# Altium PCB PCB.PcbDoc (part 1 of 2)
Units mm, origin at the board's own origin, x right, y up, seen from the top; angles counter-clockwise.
Board outline 68.58 x 53.34 mm, 2 copper layers (TOP, BOTTOM), stack 1.636 mm thick; 84 components, 64 nets, 302 pads, 163 vias.
Unrouted connection lines stored in the file: 1.
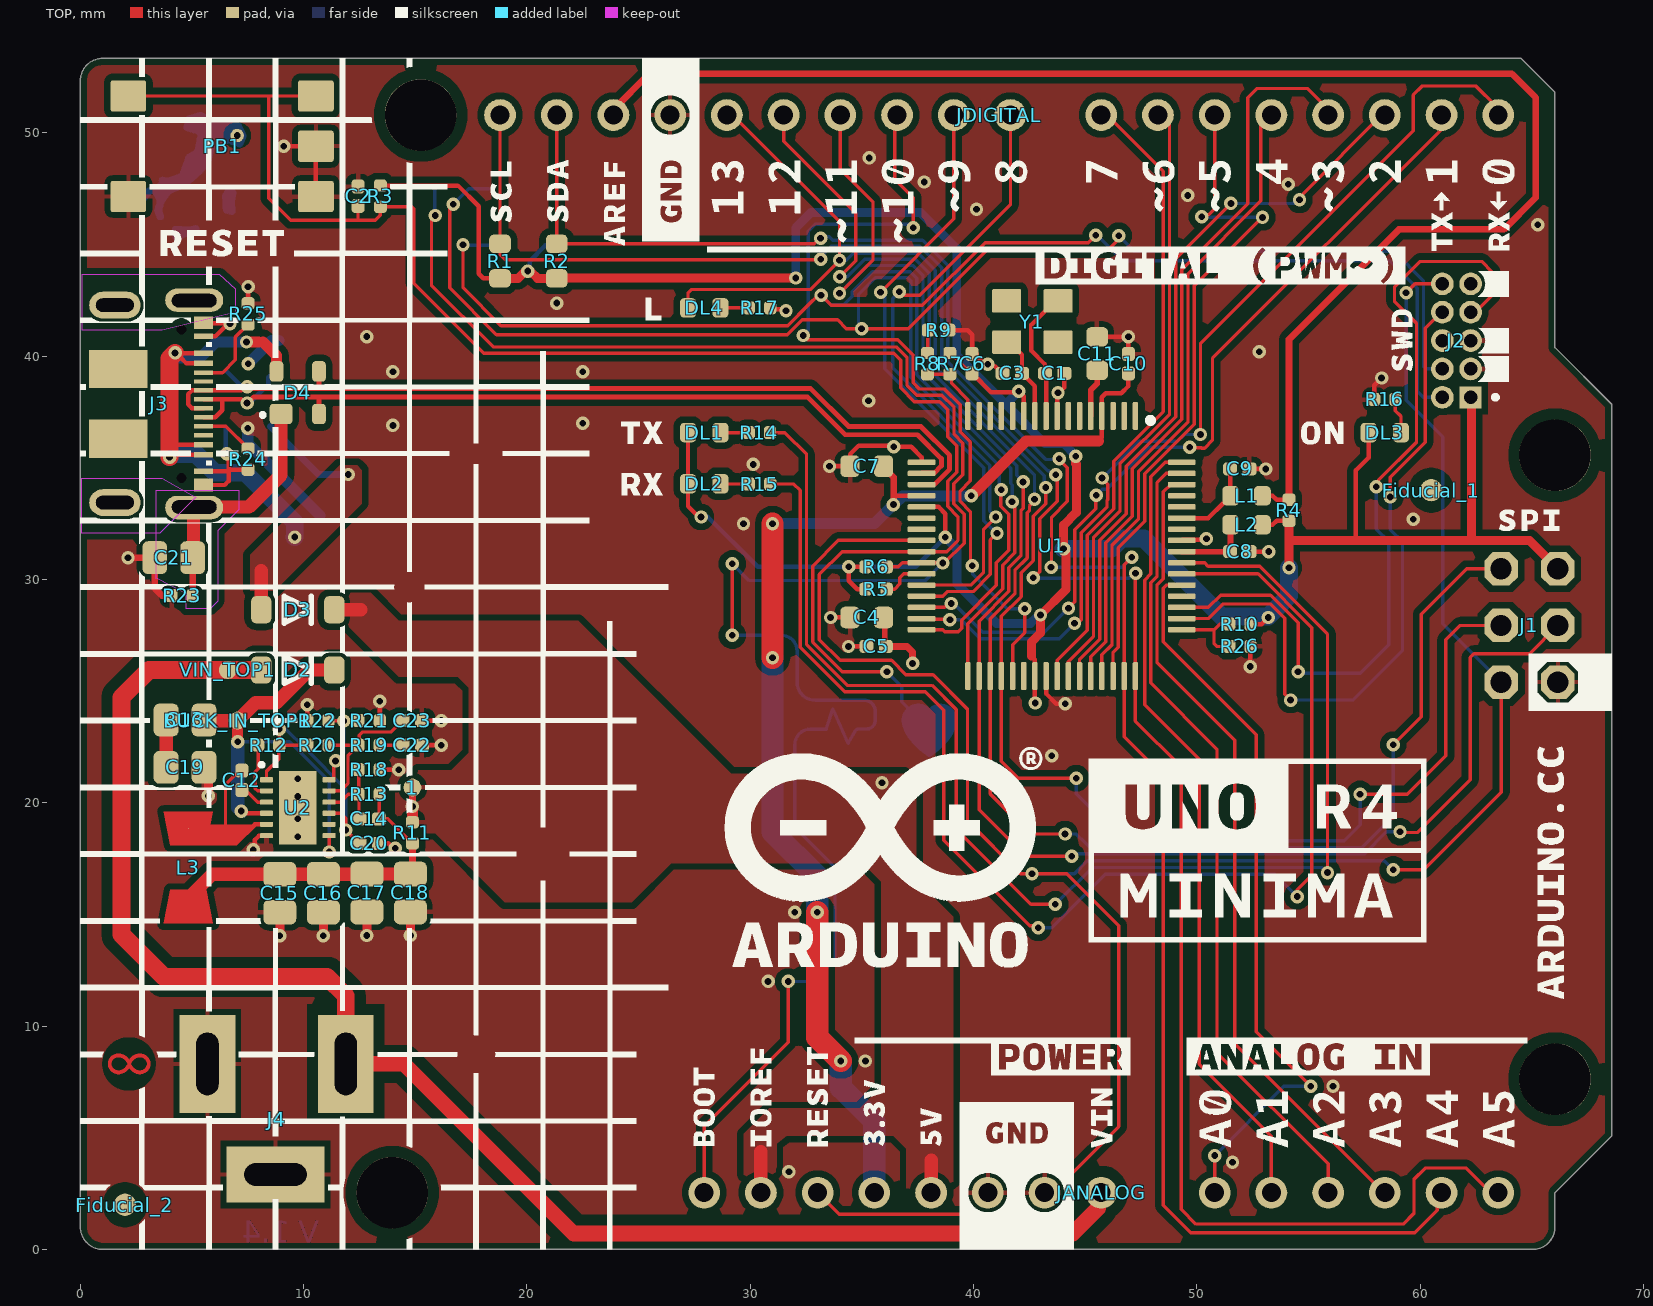
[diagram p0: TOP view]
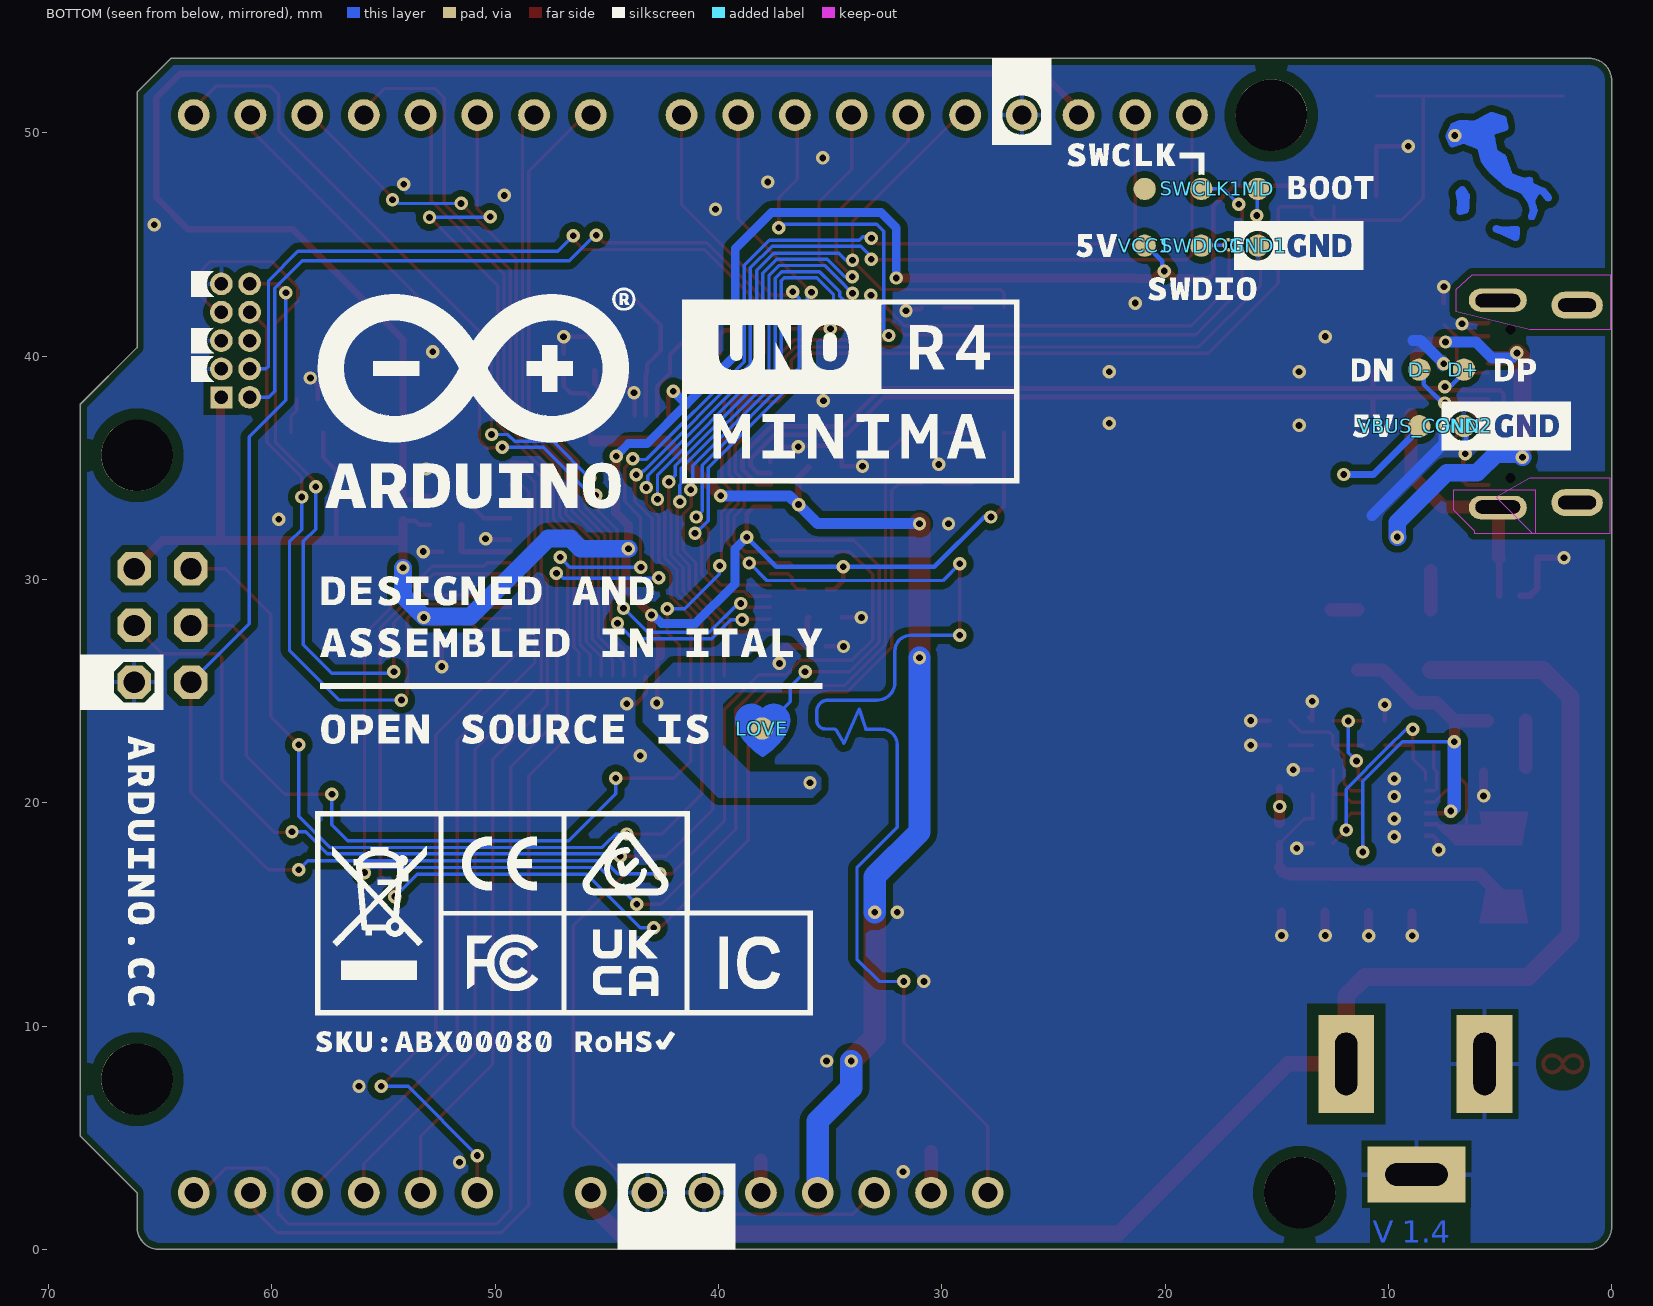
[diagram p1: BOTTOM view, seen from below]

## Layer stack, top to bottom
Top Solder: solder mask 0.025, SM-003, Dk 4
TOP: signal copper 0.018
Dielectric2: core 1.6, FR-4, Dk 4.8
BOTTOM: signal copper 0.018
Bottom Solder: solder mask 0.025, SM-003, Dk 4

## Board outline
0,1 0,52.34 cw(c1,52.34) 1,53.34 64.516,53.34 66.04,51.816 66.04,40.386 68.58,37.846 68.58,5.08 66.04,2.54 66.04,1 cw(c65.04,1) 65.04,0 1,0 cw(c1,1)

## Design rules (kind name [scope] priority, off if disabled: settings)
BoardOutlineClearance Mousebites [(ObjectKind = 'Pad') And (Name = 'Free-MOUSEBITE')] p1: gap=0 ignorepadtopadclearanceinfootprint=FALSE
BoardOutlineClearance Silks [(OnLayer('Top Overlay') OR OnLayer('Bottom Overlay'))] p2: gap=0 ignorepadtopadclearanceinfootprint=FALSE
BoardOutlineClearance [All] p3: gap=0.3 ignorepadtopadclearanceinfootprint=FALSE
Clearance [(ObjectKind = 'Region') And (Net = 'No Net') And (Area = '1.358 sq.')] p1: gap=0.15 ignorepadtopadclearanceinfootprint=FALSE
Clearance MH [(ObjectKind = 'Pad') And (Name = 'Free-MH')] p2: gap=0.5 ignorepadtopadclearanceinfootprint=FALSE
Clearance COPPER_0.3mm_VIN [InNet('GND') vs InNet('VIN')] p3: gap=0.5 ignorepadtopadclearanceinfootprint=TRUE except(0.127: Arc-Arc Arc-Track Arc-SMDPad Arc-THPad Arc-Via Arc-Text Arc-Hole Track-Track Track-SMDPad Track-THPad Track-Via Track-Text Track-Hole SMDPad-SMDPad SMDPad-THPad SMDPad-Via SMDPad-Text SMDPad-Hole THPad-THPad THPad-Via THPad-Text THPad-Hole Via-Via Via-Text Via-Hole Fill-Hole Poly-Hole Region-Hole Text-Text Text-Hole)
Clearance COPPER_0.3mm [All] p4: gap=0.127 ignorepadtopadclearanceinfootprint=FALSE except(0.3: Arc-Fill Arc-Poly Arc-Region Track-Fill Track-Poly Track-Region SMDPad-Fill SMDPad-Poly SMDPad-Region THPad-Fill THPad-Poly THPad-Region Via-Fill Via-Poly Via-Region Fill-Fill Fill-Poly Fill-Region Poly-Poly Poly-Region Region-Region)
Clearance "Generic clearance 0.15mm" [All] p5: gap=0.15 ignorepadtopadclearanceinfootprint=FALSE
ComponentClearance DoubleResP119 [(ObjectKind = 'Component') And (Name = 'R119') vs (ObjectKind = 'Component') And (Name = 'R120')] p1: gap=0 collisioncheckmode=3 verticalgap=0 showdistances=FALSE
ComponentClearance DoubleResP300 [(ObjectKind = 'Component') And (Name = 'R117') vs (ObjectKind = 'Component') And (Name = 'R115')] p2: gap=0 collisioncheckmode=3 verticalgap=0 showdistances=FALSE
ComponentClearance DoubleResP108 [(ObjectKind = 'Component') And (Name = 'R114') vs (ObjectKind = 'Component') And (Name = 'R116')] p3: gap=0 collisioncheckmode=3 verticalgap=0 showdistances=FALSE
ComponentClearance ComponentClearance_2 [InComponent('J4')] p4: gap=0 collisioncheckmode=3 verticalgap=0 showdistances=FALSE
ComponentClearance ComponentClearance_1 [InComponent('Fiducial_2') vs InComponent('J3')] p5: gap=0 collisioncheckmode=3 verticalgap=0 showdistances=FALSE
ComponentClearance [All] p6: gap=0.2 collisioncheckmode=3 verticalgap=0 showdistances=TRUE
DiffPairsRouting USB [InDifferentialPairClass('USB')] p1: maxlimit=0.15 minlimit=0.15 mostfreqgap=0.15 toplayer_minwidth=0.22 toplayer_maxwidth=0.22 toplayer_prefwidth=0.22 bottomlayer_minwidth=0.2 bottomlayer_maxwidth=0.2 bottomlayer_prefwidth=0.2 impedanceprofiledriven=TRUE impedanceprofileid={E6B00C31-4C8E-439C-824F-D2B2CDC26F9C} impedanceprofilevalue=90.000000 maxuncoupledlength=12.7
Height [All] p1: minheight=0 maxheight=30 prefheight=12.7
HoleSize [All] p1: absolutevalues=TRUE maxlimit=30 minlimit=0.3 maxpercent=80.000 minpercent=20.000
HoleToHoleClearance [All] p1: gap=0.25 allowstackedmicrovias=FALSE
MinimumAnnularRing [All] p1: minimumring=0.15
MinimumSolderMaskSliver [All] p1: minsoldermaskwidth=0.22
PlaneConnect [All] p1: pad.planeconnectstyle=Relief pad.reliefexpansion=0.508 pad.reliefentries=4 pad.reliefconductorwidth=0.254 pad.reliefairgap=0.254 via.planeconnectstyle=Direct via.reliefexpansion=0.508 via.reliefentries=4 via.reliefconductorwidth=0.254 via.reliefairgap=0.254
PolygonConnect [All] p1: thpad.connectstyle=Relief thpad.reliefconductorwidth=0.2 thpad.reliefentries=4 thpad.polygonreliefangle="90 Angle" thpad.airgapwidth=0.254 smdpad.connectstyle=Relief smdpad.reliefconductorwidth=0.2 smdpad.reliefentries=4 smdpad.polygonreliefangle="90 Angle" smdpad.airgapwidth=0.254 via.connectstyle=Direct via.reliefconductorwidth=0.254 via.reliefentries=4 via.polygonreliefangle="90 Angle" via.airgapwidth=0.254
RoomDefinition designers_1 [False vs False] p1: confinementstyle=ConfineIn formatcopy=TRUE lockcomponents=FALSE outline 0.4,10.2 4,10.2 4,5.8 0.4,5.8
RoomDefinition TOP [InComponentClass('TOP')] p2: confinementstyle=ConfineIn formatcopy=TRUE lockcomponents=FALSE outline 69.7,-1.1 85.9,-1.1 85.9,12.7 69.7,12.7
RoutingVias StandardVias [All] p1: holewidth=0.3 width=0.6 viastyle="Through Hole" minholewidth=0.3 minwidth=0.6 maxholewidth=0.3 maxwidth=0.6
ShortCircuit SolderJumper [Component = 'SJ2' vs (InNet('VCC') OR InNet('NetL3_1'))] p1: allowed=TRUE
ShortCircuit [All] p2: allowed=FALSE
SilkToSilkClearance [All] p1: silktosilkclearance=0.2
SilkToSolderMaskClearance [IsPad] p1: minsilkscreentomaskgap=0.15 clearancetoexposedcopper=TRUE
SolderMaskExpansion VIAtented [IsVia] p1: expansion=0.102 istentingtop=TRUE
SolderMaskExpansion [All] p2: expansion=0.05 istentingtop=FALSE
UnConnectedPin [All] p1:
UnRoutedNet [NOT WithinRoom('designers_1')] p1: checkbadconnections=TRUE
ViasUnderSMD [All] p1: allowed=FALSE
Width StandardTraces [All] p1: maxlimit=5 minlimit=0.15 preferedwidth=0.15 minimp=50.000000 maximp=50.000000 favimp=50.000000
19 further rules are at their usual default settings.

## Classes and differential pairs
differential pair class USB: USB_D_1
differential pair USB_D_1: +USB_D_1_P -USB_D_1_N

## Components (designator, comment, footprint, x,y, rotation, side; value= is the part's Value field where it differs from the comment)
1 "CMP-018-0004-A.4" TP-0.8MM 14.873,20.682 r90 top
BUCK_IN_TOP1 "CMP-018-0004-A.4" TP-0.8MM 7.038,23.682 r90 top
C1 "C0402C150J5GACTU" CAP-0402 43.638,39.231 r0 top value=15pF
C2 "DNP" CAP-0402 12.438,47.166 r90 top
C3 "C0402C150J5GACTU" CAP-0402 41.738,39.231 r180 top value=15pF
C4 "GRM188R61C475KAAJD" CAP-0603 35.22,28.3 r0 top value=4.7µF
C5 "GRM155R61H104KE19D" CAP-0402 35.638,27 r0 top value=100nF
C6 "GRM155R61H104KE19D" CAP-0402 39.938,39.666 r270 top value=100nF
C7 "GRM188R61C475KAAJD" CAP-0603 35.22,35.076 r0 top value=4.7µF
C8 "GRM155R61H104KE19D" CAP-0402 51.928,31.25 r180 top value=100nF
C9 "CL05A105KP5NNNC" CAP-0402 51.928,34.95 r0 top value=1µF
C10 "GRM155R61H104KE19D" CAP-0402 46.938,39.666 r270 top value=100nF
C11 "GRM188R61C475KAAJD" CAP-0603 45.538,40.116 r270 top value=4.7µF
C12 "GRM155R61H104KE19D" CAP-0402 7.238,21.007 r270 top value=100nF
C13 "CL21A226MAQNNNE" CAP-0805 4.691,23.708 r0 top value=22µF
C14 "GRM1555C1H330JA01D" CAP-0402 12.938,19.282 r0 top value=33pF
C15 "CL21A226MAQNNNE" CAP-0805 8.936,15.947 r90 top value=22µF
C16 "CL21A226MAQNNNE" CAP-0805 10.886,15.947 r90 top value=22µF
C17 "CL21A226MAQNNNE" CAP-0805 12.834,15.962 r90 top value=22µF
C18 "CL21A226MAQNNNE" CAP-0805 14.784,15.962 r90 top value=22µF
C19 "CL21A226MAQNNNE" CAP-0805 4.691,21.591 r180 top value=22µF
C20 "CL05A105KP5NNNC" CAP-0402 12.938,18.182 r0 top value=1µF
C21 "FV21X472K102ECG" CAP-0805 4.184,30.978 r0 top value=4.7nF
C22 "GRM155R71H102KA01D" CAP-0402 14.873,22.582 r180 top value=1nF
C23 "CC0402JRNPO9BN101" CAP-0402 14.873,23.682 r180 top value=100pF
D2 "PMEG6020AELRX" SOD123-1 9.738,25.947 r180 top
D3 "PMEG6020AELRX" SOD123-1 9.738,28.647 r180 top
D4 "PRTR5V0U2X,215" SOT190P230X110-4N 9.738,38.366 r0 top
D+ "CMP-018-0005-A.3" TP-1.00MM#1 6.615,39.4 r180 bottom
D- "CMP-018-0005-A.3" TP-1.00MM#1 8.615,39.4 r180 bottom
DL1 "KPT-1608YC" LEDC1608X80N-AK#1 27.94,36.576 r180 top
DL2 "KPT-1608YC" LEDC1608X80N-AK#1 27.94,34.29 r180 top
DL3 "HSMG-C190" LEDC1608X80N-AK#2 58.42,36.576 r180 top
DL4 "KPT-1608YC" LEDC1608X80N-AK#1 27.94,42.164 r180 top
Fiducial_1 "Fiducial mark 1mm with 2mm solder" "Fiducial mark 1mm with circle-Footprint-1" 60.5,34 r90 top
Fiducial_2 "Fiducial mark 1mm with 2mm solder" "Fiducial mark 1mm with circle-Footprint-1" 2,2 r90 top
GND1 "CMP-018-0005-A.3" TP-1.00MM#2 15.835,44.95 r90 bottom
GND2 "CMP-018-0005-A.3" TP-1.00MM#1 6.615,36.875 r90 bottom
J1 "PH2-06-UA" 2X03 64.897,27.94 r90 top
J2 "HPH2-A-10-SGA" PINHEAD_2X05_127 61.63,40.7 r180 top
J3 "CX90B-16P" CX90B-16P-Footprint-1 3.538,37.866 r270 top
J4 "19TW-746" POWERSUPPLY_DC-21MM 5.69,8.306 r0 top locked
JANALOG "20TW-995" 1X14-CUSTOM 45.72,2.54 r0 top locked
JDIGITAL "20TW-994" 1X18-CUSTOM 45.72,50.8 r180 top locked
L1 "BLM18PG471SN1D" L-0603 52.228,33.75 r180 top
L2 "BLM18PG471SN1D" L-0603 52.228,32.45 r180 top
L3 "PMF42-103MN" PMF42 4.836,17.099 r270 top
LOVE "CMP-018-0005-A.3" TP-1.00MM#2 38.045,23.326 r90 bottom
MD "CMP-018-0005-A.3" TP-1.00MM#2 15.835,47.49 r90 bottom
PB1 "1571636-3" TS42 6.35,49.403 r0 top locked
R1 "CR0603AFX-5101EAS" RES-0603 18.796,44.259 r270 top value=5.1k
R2 "CR0603AFX-5101EAS" RES-0603 21.336,44.259 r270 top value=5.1k
R3 "RC0402FR-075K1L" RES-0402 13.438,47.166 r90 top value=5.1k
R4 "RC0402FR-075K1L" RES-0402 54.128,33.1 r270 top value=5.1k
R5 "RC0402FR-075K1L" RES-0402 35.638,29.566 r0 top value=5.1k
R6 "RC0402FR-075K1L" RES-0402 35.638,30.566 r0 top value=5.1k
R7 "RC0402FR-075K1L" RES-0402 38.938,39.666 r90 top value=5.1k
R8 "RC0402FR-075K1L" RES-0402 37.938,39.666 r270 top value=5.1k
R9 "RC0402FR-075K1L" RES-0402 38.438,41.166 r180 top value=5.1k
R10 "WF04H1003BT" RES-0402 51.928,28 r0 top value=100k
R11 "CRCW04020000Z0EDC" RES-0402 14.873,18.657 r90 top value=0
R12 "CRCW04020000Z0EDC" RES-0402 8.438,22.582 r0 top value=0
R13 "CRCW0402100KFKEDC" RES-0402 12.938,20.382 r180 top value=100k
R14 "CRCW0402330RJNED" RES-0402 30.413,36.576 r180 top value=330
R15 "CRCW0402330RJNED" RES-0402 30.42,34.276 r180 top value=330
R16 "CRCW0402330RJNED" RES-0402 58.42,38.066 r0 top value=330
R17 "CRCW0402330RJNED" RES-0402 30.42,42.164 r180 top value=330
R18 "RC0402FR-0713K7L" RES-0402 12.938,21.482 r180 top value=13.7k
R19 "AC0402FR-07249KL" RES-0402 12.938,22.582 r180 top value=249k
R20 "CRCW04020000Z0EDC" RES-0402 10.638,22.582 r180 top value=0
R21 "CRCW0402100KFKEDC" RES-0402 12.938,23.682 r180 top value=100k
R22 "CRCW0402100KFKEDC" RES-0402 10.638,23.682 r0 top value=100k
R23 "CRCW04021M00FKED" RES-0402 4.559,29.278 r0 top value=1M
R24 "RC0402FR-075K1L" RES-0402 7.513,35.391 r90 top value=5.1k
R25 "RC0402FR-075K1L" RES-0402 7.513,41.891 r270 top value=5.1k
R26 "WF04H1372BTL" RES-0402 51.928,27 r180 top value=13.7k
SWCLK1 "CMP-018-0005-A.3" TP-1.00MM#1 18.375,47.49 r90 bottom
SWDIO1 "CMP-018-0005-A.3" TP-1.00MM#1 18.375,44.95 r90 bottom
U1 "R7FA4M1AB3CFM#AA0" CQFP50P1200X1200X170-64L 43.5,31.5 r270 top locked
U2 "ISL854102FRZ-T" QFN0P300X400X100_HS-13L 9.738,19.782 r0 top
VBUS_CONN "CMP-018-0005-A.3" TP-1.00MM#1 8.615,36.86 r90 bottom
VCC1 "CMP-018-0005-A.3" TP-1.00MM#2 20.915,44.95 r90 bottom
VIN_TOP1 "CMP-018-0004-A.4" TP-0.8MM 6.603,25.947 r90 top
Y1 "FTX16.000M12SM3S-30/30" CRYSTAL_3.2x2.5mm_16MHz 42.638,41.551 r0 top

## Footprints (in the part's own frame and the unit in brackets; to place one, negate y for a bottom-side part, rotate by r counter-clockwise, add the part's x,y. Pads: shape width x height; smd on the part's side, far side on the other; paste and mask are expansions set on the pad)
1X14-CUSTOM [mil]
  round 56 hole 33.46: 1(-700,0) 2(-600,0) 3(-500,0) 4(-400,0) 5(-300,0) 6(-200,0) 7(-100,0) 8(0,0) 9(200,0) 10(300,0) 11(400,0) 12(500,0) 13(600,0) 14(700,0)
  body extent -760,-50 759,50, height 335
1X18-CUSTOM [mil]
  round 56 hole 33.46: 1(-700,0) 2(-600,0) 3(-500,0) 4(-400,0) 5(-300,0) 6(-200,0) 7(-100,0) 8(0,0) 9(160,0) 10(260,0) 11(360,0) 12(460,0) 13(560,0) 14(660,0) 15(760,0) 16(860,0) 17(960,0) 18(1060,0)
  body extent -758,-50 1120,50, height 335
2X03 [mm]
  oct 1.501x1.501 / inner oct 1.524x1.524 / far side oct 1.501x1.501 hole 0.95: 1(2.54,1.27) 2(2.54,-1.27) 3(0,1.27) 4(0,-1.27) 5(-2.54,1.27) 6(-2.54,-1.27)
  body extent -3.81,-2.54 3.81,2.5, height 8.5
CAP-0402 [mm] "Chip Capacitor, 2-Leads, Body  0402 (in) 1005 (mm), IPC Medium Density"
  rrect52% 0.63x0.58 smd mask+0.05: 1(-0.435,0) 2(0.435,0)
  body extent -0.5,-0.25 0.5,0.25, height 0.5
CAP-0603 [mm] "Chip Capacitor, Body 0603 imperial,1.6x0.8mm, IPC High Density"
  rrect51% 0.87x0.97 smd mask+0.05: 1(-0.75,0) 2(0.75,0)
  body extent -0.8,-0.4 0.8,0.4, height 0.8
CAP-0805 [mm] "Chip Capacitor, Body 0805 imperial, 2.0x1.2mm, IPC Medium Density"
  rrect45% 1.11x1.47 smd mask+0.05: 1(-0.85,0) 2(0.85,0)
  body extent -1,-0.62 1,0.63, height 1.25
CQFP50P1200X1200X170-64L [mm] "CQFP, 64-Leads, Body 12,00x12,00mm, Pitch 0,50mm, IPC High Density"
  rrect50% 1.25x0.25 smd mask+0.05: 1(-5.825,3.75) 2(-5.825,3.25) 3(-5.825,2.75) 4(-5.825,2.25) 5(-5.825,1.75) 6(-5.825,1.25) 7(-5.825,0.75) 8(-5.825,0.25) 9(-5.825,-0.25) 10(-5.825,-0.75) 11(-5.825,-1.25) 12(-5.825,-1.75) 13(-5.825,-2.25) 14(-5.825,-2.75) 15(-5.825,-3.25) 16(-5.825,-3.75) 33(5.825,-3.75) 34(5.825,-3.25) 35(5.825,-2.75) 36(5.825,-2.25) 37(5.825,-1.75) 38(5.825,-1.25) 39(5.825,-0.75) 40(5.825,-0.25) 41(5.825,0.25) 42(5.825,0.75) 43(5.825,1.25) 44(5.825,1.75) 45(5.825,2.25) 46(5.825,2.75) 47(5.825,3.25) 48(5.825,3.75)
  rrect50% 0.25x1.25 smd mask+0.05: 17(-3.75,-5.825) 18(-3.25,-5.825) 19(-2.75,-5.825) 20(-2.25,-5.825) 21(-1.75,-5.825) 22(-1.25,-5.825) 23(-0.75,-5.825) 24(-0.25,-5.825) 25(0.25,-5.825) 26(0.75,-5.825) 27(1.25,-5.825) 28(1.75,-5.825) 29(2.25,-5.825) 30(2.75,-5.825) 31(3.25,-5.825) 32(3.75,-5.825) 49(3.75,5.825) 50(3.25,5.825) 51(2.75,5.825) 52(2.25,5.825) 53(1.75,5.825) 54(1.25,5.825) 55(0.75,5.825) 56(0.25,5.825) 57(-0.25,5.825) 58(-0.75,5.825) 59(-1.25,5.825) 60(-1.75,5.825) 61(-2.25,5.825) 62(-2.75,5.825) 63(-3.25,5.825) 64(-3.75,5.825)
  silkscreen extent -5.75,4.3 -5.5,4.55, body extent -6.1,-6.1 6.1,6.1, height 1.67
CRYSTAL_3.2x2.5mm_16MHz [mm]
  rrect10% 1.3x1.05 smd: 1(-1.15,-0.925) 2(1.15,-0.925) 3(1.15,0.925) 4(-1.15,0.925)
  body extent -1.6,-1.25 1.6,1.25, height 0.8
CX90B-16P-Footprint-1 [mm]
  rect 0.57x0.85 smd mask+0.05: A1(-3.635,1.988) A12(3.635,1.988)
  rect 0.25x0.85 smd mask+0.05: A4(-2.275,1.988) A9(2.275,1.988) B1(3.025,1.988) B4(1.825,1.988) B9(-1.825,1.988) B12(-3.025,1.988)
  rect 0.2x0.85 smd mask+0.05: A5(-1.4,1.988) A6(-0.6,1.988) A7(0.6,1.988) A8(1.4,1.988) B5(1,1.988) B6(0.2,1.988) B7(-0.2,1.988) B8(-1,1.988)
  round 0.2 hole 0.45 unplated paste-50 mask+0.2: FIXING(-3.32,0.988) FIXING(3.32,0.988)
  rect 1.71x2.6 smd paste-0.3 mask+0.05: FIXING(-1.565,-1.837) FIXING(1.565,-1.837)
  oval 1.05x2.6 hole 0.6 slot 2 at 90 deg copper offset -0.025,0 mask+0.05: SHIELD1(-4.62,1.563)
  oval 1.05x2.6 hole 0.6 slot 2 at 90 deg copper offset 0.025,0 mask+0.05: SHIELD2(4.62,1.563)
  oval 1.2x2.3 hole 0.6 slot 1.7 at 90 deg mask+0.05: SHIELD3(-4.42,-1.987) SHIELD4(4.42,-1.987)
  body extent -4.77,-4.4 4.77,2.4, height 3.17
"Fiducial mark 1mm with circle-Footprint-1" [mm]
  round 1 smd paste-10 mask+0.5: 1(0,0)
  TOP pour cut-out: 0,1 0.383,0.924 0.707,0.707 0.924,0.383 1,0 1,0 0.924,-0.383 0.707,-0.707 0.383,-0.924 0,-1 0,-1 -0.383,-0.924 -0.707,-0.707 -0.924,-0.383 -1,0 -1,0 -0.924,0.383 -0.707,0.707 -0.383,0.924 0,1
L-0603 [mm] "Chip Inductor - Body 0603 imperial,1.6x0.8mm, IPC High Density"
  rrect51% 0.75x0.87 smd mask+0.05: 1(-0.71,0) 2(0.71,0)
  body extent -0.8,-0.4 0.8,0.4, height 0.8
LEDC1608X80N-AK#1 [mm]
  rrect50% 0.72x0.87 smd: A(0.725,0) C(-0.725,0)
  body extent -0.8,-0.4 0.8,0.4, height 0.79
LEDC1608X80N-AK#2 [mm]
  rrect50% 0.72x0.87 smd mask+0.05: A(0.725,0) C(-0.725,0)
  body extent -0.8,-0.4 0.8,0.4, height 0.79
PINHEAD_2X05_127 [mil]
  rect 38.73x38.73 / inner rect 38.74x38.74 / far side rect 38.73x38.73 hole 23.62: 1(-25,100)
  round 40 hole 23.62: 2(25,100) 3(-25,50) 4(25,50) 5(-25,0) 6(25,0) 7(-25,-50) 8(25,-50) 9(-25,-100) 10(25,-100)
  silkscreen extent -70,98 -67,102, body extent -68,-125 68,125, height 158
PMF42 [mil]
  round 1 smd mask+1.97: 1(-68.9,0) 2(68.9,0)
  TOP region: 39.37,31.5 39.37,-31.5 98.43,-43.31 98.43,43.31
  TOP region: -39.37,31.5 -39.37,-31.5 -98.43,-43.31 -98.43,43.31
  body extent -94,-94 94,94, height 81
POWERSUPPLY_DC-21MM [mm]
  rect 2.5x4.4 hole 1 slot 2.8 at 90 deg: 1(6.2,0) 3(0,0)
  rect 4.4x2.5 hole 1 slot 2.8 at 0 deg: 2(3.05,-4.95)
  body extent -7.65,-4.85 6.75,4.55, height 3
QFN0P300X400X100_HS-13L [mm] "QFN, 12-Leads, Body 3.00x4.00mm, Pitch 0.00mm/0.50mm, Thermal Pad 1.68x3.28mm, IPC High Density"
  rrect50% 0.6x0.23 smd mask+0.05: 1(-1.4,1.25) 2(-1.4,0.75) 3(-1.4,0.25) 4(-1.4,-0.25) 5(-1.4,-0.75) 6(-1.4,-1.25) 7(1.4,-1.25) 8(1.4,-0.75) 9(1.4,-0.25) 10(1.4,0.25) 11(1.4,0.75) 12(1.4,1.25)
  rect 1.7x3.3 smd paste-50 mask+0.05: 13(0,0)
  silkscreen extent -1.67,1.87 -1.57,1.97, body extent -1.5,-2 1.5,2, height 1
RES-0402 [mm] "Chip Resistor, 2-Leads, Body  0402 (in) 1005 (mm), IPC Medium Density"
  rrect51% 0.55x0.58 smd mask+0.05: 1(-0.475,0) 2(0.475,0)
  body extent -0.5,-0.25 0.5,0.25, height 0.34
RES-0603 [mm] "Chip Resistor - Body 0603 imperial,1.6x0.8mm, IPC High Density"
  rrect51% 0.82x0.97 smd mask+0.05: 1(-0.775,0) 2(0.775,0)
  body extent -0.8,-0.4 0.8,0.4, height 0.43
SOD123-1 [mm]
  rrect50% 0.91x1.22 smd: A(1.635,0) C(-1.635,0)
  silkscreen extent -0.6,-0.6 0.6,0.6, body extent -1.85,-1 1.85,1, height 1.2
SOT190P230X110-4N [mm]
  rrect33% 1.01x0.91 smd paste+0 mask+0.05: 1(-0.75,-0.955)
  rrect49% 0.61x0.91 smd paste+0 mask+0.05: 2(0.95,-0.955) 3(0.95,0.955) 4(-0.95,0.955)
  silkscreen extent -1.62,-1.05 -1.52,-0.95, body extent -1.45,-1.15 1.45,1.15, height 1
TP-0.8MM [mil]
  rrect100% 31.5x31.5 smd paste-196.85 mask+1.97: X(0,0)
TP-1.00MM#1 [mm]
  rrect100% 1x1 smd paste-2.54 mask+0.05: X(0,0)
TP-1.00MM#2 [mm]
  rrect100% 1x1 smd paste-2.54: X(0,0)
TS42 [mm]
  rrect15% 1.6x1.4 smd: 1(4.2,-2.25) 2(-4.2,-2.25) 3(4.2,2.25) 4(-4.2,2.25)
  rrect15% 1.6x1.4 smd paste+0: 5(4.2,0)
  body extent -4.1,-3.25 4.1,3.25, height 2.6

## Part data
1 BUCK_IN_TOP1 VIN_TOP1: library part UT0012-A.4, "Test point 0.8mm"
C1 C3: library part C0025-A.16, "CAP CHIP 0402 15pF 5% 50V C0G", Case Code (Imperial)=0402, Dielectric=C0G, Manufacturer=KEMET, Tolerance=5%, Voltage=50V
C2: library part UT0021-A.3, Package=0402
C4 C7 C11: library part C0054-A.16, "CAP CHIP 0603 4.7uF 10% 16V X5R", Case Code (Imperial)=0603, Dielectric=X5R, Manufacturer=Murata, Manufacturer 3="Samsung Electro-Mechanics", Part number 2=GRM188R61C475KE11D, Part number 3=CL10A475KO8NNNC, Tolerance=10%, Voltage=16V
C5 C6 C8 C10 C12: library part C0015-A.14, "CAP CHIP 0402 100nF 10% 50V X5R", Case Code (Imperial)=0402, Dielectric=X5R, Manufacturer=Murata, Tolerance=10%, Voltage=50V
C9 C20: library part C0017-A.14, "CAP CHIP 0402 1uF 10% 10V X5R", Case Code (Imperial)=0402, Dielectric=X5R, Manufacturer="Samsung Electro-Mechanics", Manufacturer 2="Murata Electronics", Part number 2=GCM155C71A105KE38D, Tolerance=10%, Voltage=10V
C13 C15 C16 C17 C18 C19: library part C0111-A.7, "CAP CHIP 0805 22uF 20% 25V X5R", Case Code (Imperial)=0805, Dielectric=X5R, Manufacturer="Samsung Electro-Mechanics", Tolerance=20%, Voltage=25V
C14: library part C0034-A.14, "CAP CHIP 0402 33pF 5% 50V C0G", Case Code (Imperial)=0402, Dielectric=C0G, Manufacturer=Murata, Tolerance=5%, Voltage=50V
C21: library part C0059-A.14, "CAP CHIP 0805 4.7nF 10% 1000V X7R", Case Code (Imperial)=0805, Dielectric=X7R, Manufacturer="PSA Shenzen", Manufacturer 2=KEMET, Part number 2=C0805V472KDRACTU, Part number 3=C0805C472KDRACTU, Tolerance=10%, Voltage=1kV
C22: library part C0007-A.15, "CAP CHIP 0402 1nF 10% 50V X7R", Case Code (Imperial)=0402, Dielectric=X7R, Manufacturer=KEMET, Tolerance=10%, Voltage=50V
C23: library part C0013-A.4, "CAP CHIP 0402 100pF 10% 50V C0G", Case Code (Imperial)=0402, Dielectric=C0G, Manufacturer=Yageo, Tolerance=5%, Voltage=50V
D2 D3: library part D0026-A.6, "DIODE SCHOTTKY SMD 2A 60V SOD123FL", Forward Current=2A, Forward Voltage=0.6V, Manucturer Part Number 2=SS26L, Manufacturer=Nexperia
D4: library part D0025-A.5, "TVS ARRAY 4LIN.8kV 1pF SOT143B", Manufacturer=Nexperia
D+ D- GND1 GND2 LOVE MD SWCLK1 SWDIO1 VBUS_CONN VCC1: library part UT0013-A.4, "Test point 1.00mm"
DL1 DL2 DL4: library part L0008-A.5, "LED SMD 0603 GIA588   8mcd 120^", Manufacturer=Kingbright
DL3: library part L0009-A.5, "LED SMD 0603 GREEN/568 15mcd 120^", Manufacturer=Broadcom
Fiducial_1 Fiducial_2: library part UT0024-A.6
J1: library part J0004-A.5, "CONN Header Through Hole 6 position 0.100\" (2.54mm)", Manufacturer="Adam Tech"
J2: library part J0068-A.9, "CONN CONN STRIP THD 1,27 M/2/D 10v AuF H6,3 JTAG", Manufacturer="Adam Tech"
J3: library part J0272-A.3, "CONN RCPT USB3.1 TYPEC 16POS SMD", Manufacturer=Hirose
J4: library part J0236-A.5, "CONN PWR JACK 2.1X5.5MM SOLDER", Manufacturer=4UCON
JANALOG: library part J0063-A.7, "CONN STRIP F/1/D 14v SER.NERA s1pin", Manufacturer=4UCONN
JDIGITAL: library part J0035-A.10, "CONN STRIP F/1/D 18v SER.NERA s1pin", Manufacturer=4UCONN
L1 L2: library part I0006-A.5, "FERRITE SMD 0603 470R 1A 0.2R", Case Code (Imperial)=0603, Case Code (Metric)=1608, Current=1A, DC Resistance (DCR)=200mR, Manufacturer=Murata, Max Operating Temperature=125°C, Min Operating Temperature=-55°C, Package Quantity=1, Test Frequency=100MHz, Tolerance=25%
L3: library part I0072-A.3, "IND 10uH 20%, max 235mR, IDC 2.3A, Isat 2.3A, shielded, max 5MHz, 4.5x4.5x1.8mm", Current=2.3A, DC Resistance (DCR)=235m, Frequency=5MHz, Inductance=10µH, Manufacturer=K-WELL, Tolerance=20%
PB1: library part B0005-A.8, "PUSHBUTTON SMD 6x6 5 PINS", Manufacturer="TE Connectivity", Manufacturer 2=C&K, Manufacturer Part Number 2=TS42031-160WWS027260
R1 R2: library part R0239-A.11, "RES CHIP 0603 5k1 1% 1/10W", Case Code (Imperial)=0603, Manufacturer=Bourns, Power=100mW, Temperature Coefficient=100ppm, Tolerance=1%
R3 R4 R5 R6 R7 R8 R9 R24 R25: library part R0210-A.18, "RES CHIP 0402 5k1 1% 1/16W", Case Code (Imperial)=0402, Manufacturer=YAGEO, Power=63mW, Temperature Coefficient=100ppm, Tolerance=1%
R10: library part R0247-A.4, "RES CHIP 0402 100k 0.1% 100ppm 1/16W", Case Code (Imperial)=0402, Manufacturer=Walsin, Power=62.5mW, Temperature Coefficient=100ppm, Tolerance=0.1%
R11 R12 R20: library part R0000-A.23, "RES CHIP 0402 0R 1/16W", Case Code (Imperial)=0402, Manufacturer=Vishay, Power=62.5mW, Temperature Coefficient=0ppm, Tolerance=0%
R13 R21 R22: library part R0001-A.23, "RES CHIP 0402 100k 1% 1/16W", Case Code (Imperial)=0402, Manufacturer=Vishay, Power=62.5mW, Temperature Coefficient=100ppm, Tolerance=1%
R14 R15 R16 R17: library part R0017-A.23, "RES CHIP 0402 330R 5% 1/16W", Case Code (Imperial)=0402, Manufacturer=Vishay, Power=62.5mW, Temperature Coefficient=200ppm, Tolerance=5%
R18: library part R0233-A.9, "RES CHIP 0402 13k7 1% 1/16W", Case Code (Imperial)=0402, Manufacturer=YAGEO, Power=62.5mW, Temperature Coefficient=100ppm, Tolerance=1%
R19: library part R0234-A.8, "RES CHIP 0402 249k 1% 1/16W", Case Code (Imperial)=0402, Manufacturer=YAGEO, Power=62.5mW, Temperature Coefficient=100ppm, Tolerance=1%
R23: library part R0058-A.23, "RES CHIP 0402 1M 1% 1/16W", Case Code (Imperial)=0402, Manufacturer=Vishay, Power=62.5mW, Temperature Coefficient=100ppm, Tolerance=1%
R26: library part R0248-A.3, "RES CHIP 0402 13k7 0.1% 100PPM 1/16W", Case Code (Imperial)=0402, Manufacturer=Walsin, Power=62.5mW, Temperature Coefficient=200ppm, Tolerance=0.1%
U1: library part U0274-A.7, "IC uC RA4M1 32b M4 48MHz 254KB flash 32KB RAM 105°C LQFP64 10x10mm", Manufacturer=Renesas
U2: library part U0275-A.5, "IC BUCK Vin 40V Iout 1.2A 2MHz 12DFN 3x4mm", Manufacturer=Renesas
Y1: library part X0019-A.12, "CRYSTAL 16.0000MHz 12pF SMD", Frequency=16MHz, Manufacturer="Fronter Electronics"

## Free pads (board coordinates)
  round 1 smd far side paste-100 mask+0.05: 2(20.915,47.49)
  round 3.2 hole 3.2 unplated paste-5 mask+0.5: MH(13.97,2.54) MH(15.24,50.8) MH(66.04,7.62) MH(66.04,35.56)
  round 0.6 hole 0.3 paste-20 mask-20: TORINO(7.024,49.881)

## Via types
v1: diameter 0.6, hole 0.3, TOP to BOTTOM, tented both sides, 163 vias

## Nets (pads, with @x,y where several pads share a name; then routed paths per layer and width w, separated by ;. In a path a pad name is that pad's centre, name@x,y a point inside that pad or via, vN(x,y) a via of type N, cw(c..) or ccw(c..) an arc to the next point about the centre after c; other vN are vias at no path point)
+3V3: C7.2 C10.2 JANALOG.4 U1.4 U1.20 | length 55.5
  TOP w0.2: C7.2@35.97,35.026 C7.2@35.97,35.076 ; v1(36.415,33.355) 36.415,33.715 36.45,33.75 ; 36.428,33.728 36.45,33.75 ; U1.20@37.675,33.75 36.45,33.75 ; 45.6,36.2 45.75,36.35 U1.4@45.75,37.325 45.75,38.16 45.926,38.336 46.61,38.336 46.938,38.663 C10.2@46.938,39.231
  TOP w0.3: C7.2@35.97,35.026 36.428,34.568 36.428,33.728 36.428,33.368 v1(36.415,33.355)
  TOP w0.5: v1(39.898,33.745) 42.354,36.2 45.6,36.2
  TOP w1: v1(31,26.5) v1(31,32.5) ; v1(33.006,15.103) 33.006,9.491 v1(34.059,8.438)
  BOTTOM w0.5: v1(31,32.5) 35.56,32.5 v1(36.415,33.355) 36.442,33.355 36.832,33.745 v1(39.898,33.745)
  BOTTOM w1: v1(31,26.5) 31,18.7 33.006,16.694 v1(33.006,15.103) ; v1(34.059,8.438) 34.059,7.238 35.56,5.737 JANALOG.4@35.56,2.54
+5V: 1.X C4.2 C5.2 C6.2 D3.C DL1.A DL2.A DL3.A J1.2 J2.1 JANALOG.2 JANALOG.5 L2.1 R1.2 R2.2 R3.2 R4.2 R5.1 R6.1 R7.2 R10.2 R11.2 U1.11 U1.21 U1.39 VCC1.X | length 142.9
  TOP w0.15: R7.2@38.938,40.141 38.979,40.141 39.696,39.424 39.744,39.424 C6.2@39.938,39.231
  TOP w0.2: R3.2@13.438,47.641 16.913,47.641 17.84,46.714 17.84,43.69 18.046,43.484 R1.2@18.796,43.484 ; v1@19.936,43.813 v1(20.044,43.813) v1@20.153,43.813 ; R2.2@21.336,43.484 R2.2@21.345,43.493 ; DL1.A@27.215,36.576 DL2.A@27.215,34.29 27.215,33.285 27.7,32.8 v1(27.8,32.8) ; v1@32.03,43.493 v1(32.039,43.501) ; R6.1@35.108,30.566 v1(34.414,30.566) 34.414,29.94 34.788,29.566 R5.1@35.163,29.566 ; U1.21@37.675,33.25 38.438,33.25 38.74,32.948 v1(38.74,31.89) ; C6.2@39.938,39.231 40.793,38.375 41.976,38.375 v1(42.028,38.427) 42.25,38.205 U1.11@42.25,37.325 ; 42.598,26.568 42.75,26.417 U1.39@42.75,25.675 42.75,24.487 v1(42.77,24.468) v1@42.75,24.448 ; R10.2@52.403,28 52.9,28 v1(53.2,28.3) ; L2.1@52.938,32.45 53.39,32.45 53.574,32.633 R4.2@54.119,32.633 ; 57.128,31.75 57.128,34.892 57.695,35.459 DL3.A@57.695,36.576
  TOP w0.25: C4.2@35.97,28.3 36.022,28.248 36.022,27.052 C5.2@36.073,27
  TOP w0.3: v1(14.873,19.834) 1.X@14.873,20.682 ; C5.2@36.073,27 37.021,27 37.272,26.75 v1(37.272,26.24)
  TOP w0.4: R1.2@18.796,43.484 19.607,43.484 v1@19.936,43.813 ; v1@20.153,43.813 20.481,43.484 R2.2@21.336,43.484 ; R2.2@21.345,43.493 v1@32.03,43.493 ; 42.598,26.568 42.598,27.205 43.001,27.607 v1(43.001,28.409) 44.139,29.547 44.139,31.218 44.034,31.323 v1(44.034,31.377) 44.034,32.433 44.603,33.002 44.603,35.169 44.573,35.199 v1(44.573,35.523) ; R4.2@54.119,32.633 R4.2@54.128,32.625 v1(54.128,30.525) ; 54.128,31.825 54.203,31.75 57.128,31.75 62.3,31.75 ; J2.1@62.3,38.064 62.3,31.75 ; J1.2@66.167,30.48 64.897,31.75 62.3,31.75
  TOP w0.5: R11.2@14.873,19.132 v1(14.873,19.834)
  TOP w0.6: D3.C@11.373,28.647 12.553,28.647 ; JANALOG.2@30.48,2.54 30.48,4.38 ; JANALOG.5@38.1,2.54 38.1,4
  BOTTOM w0.2: v1(20.044,43.813) 20.121,43.889 20.121,44.251 VCC1.X@20.828,44.958 ; v1(27.8,32.8) 28.1,32.8 30.334,30.566 v1(34.414,30.566) 37.416,30.566 v1(38.74,31.89) ; 41.442,37.843 41.444,37.843
  BOTTOM w0.4: v1(32.039,43.501) 32.039,45.752 32.728,46.441 37.625,46.441 39.25,44.817 39.25,40.035 41.442,37.843 43.194,36.091 44.031,36.091 44.573,35.548 v1(44.573,35.523) ; v1(38.74,31.89) 39.267,31.363 39.267,29.796 41.031,28.033 42.547,28.033 42.824,28.309 42.847,28.309 42.947,28.409 v1(43.001,28.409) ; 41.444,37.843 v1(42.028,38.427)
  BOTTOM w0.8: v1(44.034,31.377) 46.182,31.377 46.634,31.83 47.629,31.83 51.117,28.341 53.2,28.341 54.128,29.269 v1(54.128,30.525)
  other v1: 35.9,20.9
AREF_1: JDIGITAL.16 L1.1 R4.1 | length 69
  TOP w0.2: L1.1@52.938,33.75 53.39,33.75 53.574,33.567 R4.1@54.119,33.567
  TOP w0.3: JDIGITAL.16@23.876,51.054 25.471,52.649 64.109,52.649 65.181,51.578 65.181,47.109 63.751,45.68 59.051,45.68 54.128,40.756 R4.1@54.128,33.575
CC1_1: J3.A5 R25.2 | length 3.5
  TOP w0.15: J3.A5@5.525,39.266 6.368,39.266 6.941,39.839 6.941,40.86 7.498,41.416 R25.2@7.513,41.416
CC2_1: J3.B5 R24.2 | length 2.4
  TOP w0.15: J3.B5@5.525,36.866 6.513,36.866 R24.2@7.513,35.866
GND: C1.2 C2.2 C3.2 C4.1 C5.1 C6.1 C7.1 C8.1 C9.2 C10.1 C11.1 C15.1 C16.1 C17.1 C18.1 C19.1 C20.2 C21.1 C22.1 C23.1 GND1.X GND2.X J1.6 J2.3 J2.5 J2.9 J3.A1 J3.A12 J3.B1 J3.B12 J4.2 J4.3 JANALOG.6 JANALOG.7 JDIGITAL.15 PB1.1 PB1.2 PB1.5 R9.1 R16.1 R17.1 R18.1 R21.1 R22.1 R23.1 R24.1 R25.1 R26.1 U1.8 U1.17 U1.40 U1.57 U2.6 U2.13 | length 56.7
  TOP w0.2: J3.A12@5.525,34.231 6.462,34.231 6.638,34.407 6.638,34.841 ; J3.B1@5.525,34.841 6.638,34.841 ; J3.B12@5.525,40.891 6.05,40.891 v1@6.612,41.453 ; J3.A1@5.525,41.501 5.549,41.477 6.679,41.477 v1(6.703,41.453) ; v1(6.563,35.635) 6.57,35.643 6.592,35.643 6.592,35.392 6.638,35.347 6.638,34.916 ; R24.1@7.513,34.916 6.638,34.916 ; R25.1@7.513,42.366 v1(7.513,43.112) ; v1(7.745,17.889) 7.822,17.965 7.822,18.34 7.999,18.517 8.323,18.517 U2.6@8.338,18.532 ; v1(9.109,49.403) PB1.5@10.55,49.403 PB1.1@10.55,47.153 ; R22.1@10.163,23.682 v1(10.162,24.396) ; C20.2@13.373,18.182 13.381,18.19 13.788,18.19 v1@14.01,17.967 ; v1(13.413,24.543) R21.1@13.413,23.682 R21.1@13.573,23.842 ; R18.1@13.413,21.482 13.417,21.478 14.254,21.478 v1(14.258,21.473) ; C22.1@15.308,22.582 v1(16.169,22.582) ; C23.1@15.308,23.682 v1(16.169,23.682) ; R17.1@30.895,42.164 30.961,42.098 31.539,42.098 v1(31.605,42.032) ; v1(33.549,35.076) C7.1@34.47,35.076 34.47,35.608 34.852,35.989 36.385,35.989 v1(36.435,35.94) 37.21,35.94 37.675,35.475 U1.17@37.675,35.25 ; v1(33.6,28.3) C4.1@34.47,28.3 ; v1(34.4,27) C5.1@35.203,27 ; R9.1@38.913,41.166 39.738,41.166 39.938,40.966 C6.1@39.938,40.101 ; C6.1@40.138,40.101 40.138,39.999 40.365,39.771 40.397,39.771 40.531,39.637 v1(40.64,39.637) 40.716,39.56 40.948,39.56 41.278,39.231 C3.2@41.303,39.231 ; U1.40@43.25,25.675 43.25,24.891 43.699,24.442 v1(44.111,24.442) ; U1.8@43.75,37.325 43.75,38.273 43.796,38.319 v1@43.796,38.369 ; v1(43.786,38.369) 43.845,38.369 44.073,38.597 C1.2@44.073,39.231 ; C11.1@45.538,40.866 v1(46.938,40.866) C10.1@46.938,40.101 ; U1.57@49.325,31.75 49.35,31.775 50.374,31.775 v1(50.43,31.831) ; C8.1@52.363,31.25 v1(53.228,31.25) ; C9.2@52.363,34.95 v1(53.089,34.95) ; v1(52.4,26.1) 52.401,26.101 52.401,26.999 R26.1@52.403,27 ; R16.1@57.945,38.066 57.945,38.692 v1(58.275,39.023) ; 6.638,34.841 6.638,34.916
  TOP w0.3: v1(2.134,30.978) C21.1@3.334,30.978 3.334,29.603 3.659,29.278 R23.1@4.084,29.278
  TOP w0.4: v1(5.738,20.307) 5.739,20.308 5.739,21.39 C19.1@5.741,21.391 ; v1(8.936,14.042) C15.1@8.936,15.097 ; v1(10.886,14.042) C16.1@10.886,15.097 ; v1(12.834,14.057) C17.1@12.834,15.112 ; v1(14.784,14.057) C18.1@14.784,15.112
  BOTTOM w0.2: GND2.X@6.52,36.85 6.52,35.678 v1(6.563,35.635)
  BOTTOM w0.5: v1(7.5,36.771) 7.5,36.097 10.738,32.859 ; v1(7.515,39.66) 8.555,40.7 8.9,40.7
  other v1: 31.734,3.478 51.6,3.9 56.1,7.3 35.159,8.438 30.8,12 32,15.1 14.104,17.967 9.738,18.482 9.738,19.282 9.738,20.282 9.738,21.082 43.5,22.1 29.7,32.5 59.7,32.7 30.131,35.153 14,36.9 22.5,37 35.3,38 14,39.3 22.5,39.3 52.8,40.2 12.834,40.878 21.334,42.378 65.265,45.893 40.134,46.578 49.6,47.2 54.1,47.7 37.8,47.8 35.334,48.878
MD_1: JANALOG.1 MD.X R6.2 U1.26 | length 94.1
  TOP w0.15: v1(15.9,46.3) 15.726,46.126 15.726,43.174 18.486,40.414 36.54,40.414 37.023,39.931 37.023,38.685 37.455,38.254 38.584,38.254 39.128,37.71 39.128,36.497 39.521,36.104 39.521,34.686 39.119,34.285 39.119,33.389 39.58,32.929 39.58,31.628 38.692,30.74 v1(38.617,30.74) 38.612,30.745 37.68,30.745 U1.26@37.675,30.75 36.817,30.75 36.633,30.566 R6.2@36.113,30.566 ; JANALOG.1@27.94,2.54 27.94,5.519 31.7,9.279 v1(31.7,12) ; v1(29.2,27.5) v1(29.2,30.7)
  BOTTOM w0.15: MD.X@15.835,47.49 15.868,47.458 15.868,46.332 v1(15.9,46.3) v1@15.9,46.229 ; v1@29.2,27.443 v1(29.2,27.5) 31.4,27.5 cw(c31.4,26.8) 32.1,26.8 32.1,25.394 ccw(c32.9,25.394) 32.9,24.594 35.1,24.594 cw(c35.1,24.094) 35.6,24.094 35.6,23.694 cw(c35.21,23.694) 35.21,23.304 34.842,23.304 ccw(c34.842,23.154) 34.713,23.229 34.388,22.665 33.7,24.194 33.4,23.294 32.686,23.294 ccw(c32.686,22.608) 32,22.608 32,18.9 33.8,17.1 33.8,13 32.8,12 v1(31.7,12) ; v1(29.2,30.7) 29.945,29.955 37.832,29.955 v1(38.617,30.74)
